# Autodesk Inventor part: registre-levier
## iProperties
Author: chr
Shininess: 20.0
PropertySet Name: _Private Model Information
Length Units: 11269
Angle Units: 11286
Time Units: 11279
Mass Units: 11290
Length Display Precision: 3
Angle Display Precision: 2
Compacted: False
Created: 2001-06
Part Number: registre-levier
Material: Par défaut
Document SubType Name: Modélisation
Designer: chr
Control State: 0
Master: False
Checked Out: False
PropertySet Name: Design Tracking Control
Density: 0.0
Volumn: 0.0
Area: 0.0
PropertySet Name: Model Information
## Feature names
1. Extrusion1
2. Extrusion2
3. Extrusion3
4. Extrusion4
5. Extrusion5
6. Extrusion6
7. Extrusion7
8. Extrusion8
9. Extrusion9
10. Extrusion10
11. Réseau circulaire1 [Circular Pattern]
12. Extrusion11
13. Extrusion12
14. Réseau circulaire2 [Circular Pattern]
15. Extrusion13
